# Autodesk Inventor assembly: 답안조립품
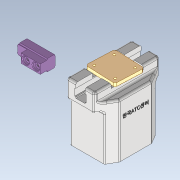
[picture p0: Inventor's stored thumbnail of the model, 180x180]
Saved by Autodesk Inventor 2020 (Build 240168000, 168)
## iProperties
Created: 2023-05
Part Number: 답안조립품
Document SubType Name: Assembly
Designer: oem
Author: oem
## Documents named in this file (8)
- C:\Users\oem\Desktop\730506V1003\답안조립품.iam
- C:\Users\oem\Desktop\730506V1003\본체.ipt
- C:\Users\oem\Desktop\730506V1003\C형 구멍용 멈춤링 60x2.ipt
- C:\Users\oem\Desktop\730506V1003\앤드캡.ipt
- C:\Users\oem\Desktop\730506V1003\피스톤.ipt
- C:\Users\oem\Desktop\730506V1003\O링 P44.ipt
- C:\Users\oem\Desktop\730506V1003\커버.ipt
- C:\Users\oem\Desktop\730506V1003\척.ipt
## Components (4 placed, 3 different names)
1. C형 구멍용 멈춤링 60x2:1
2. 피스톤:1
3. O링 P44:1
4. O링 P44:2
